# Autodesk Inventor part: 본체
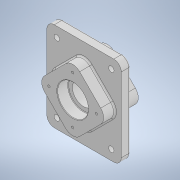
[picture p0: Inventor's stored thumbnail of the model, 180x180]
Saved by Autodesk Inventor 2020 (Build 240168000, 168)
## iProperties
Created: 2021-07
Part Number: 본체
Material: 일반
Document SubType Name: Modeling
Designer: Owner
Density: 1 g/cm^3
Appearance: 기본값
Mass: 807.977 g
Surface Area: 961.758 cm^2
Volume: 807.977 cm^3
Author: Owner
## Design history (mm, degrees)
sketch "스케치1"
  geometry: L1 (-75, -90)-(75, -90); L2 (75, -90)-(75, 90); L3 (75, 90)-(-75, 90); L4 (-75, 90)-(-75, -90); L5 (-75, -90)-(75, 90); L6 (75, -90)-(-75, 90); 1 further point
  constraints: 12 end point, 2 midpoint, 2 parallel, 1 horizontal, 1 perpendicular
  dimensions: "d0" = 150 distance of L3.end L2.end; "d1" = 180 distance of L2.end L1.end
extrude "돌출1" new body sketch "스케치1" stored distance "d2" = 18; taper "d3" = 0 deg
sketch "스케치2"
  geometry: L1 (0, 70.711)-(-70.711, 0); L2 (-70.711, 0)-(0, -70.711); L3 (0, -70.711)-(70.711, 0); L4 (70.711, 0)-(0, 70.711); L5 (0, 70.711)-(0, -70.711); L6 (-70.711, 0)-(70.711, 0); 4 further points
  constraints: 12 end point, 4 midpoint, 2 parallel, 1 coincident, 1 perpendicular, 1 vertical alignment
  dimensions: "d4" = 90 deg angle of L6 L5; "d5" = 100 distance of L1.start L1.end
extrude "돌출2" join sketch "스케치2" distance "d6" = 23; taper "d7" = 0 deg
sketch "스케치3"
  geometry: L1 (0, -70.711)-(-70.711, 0) reference; L2 (-70.711, 0)-(0, 70.711) reference; L3 (0, 70.711)-(70.711, 0) reference; L4 (70.711, 0)-(0, -70.711) reference; 1 further point
extrude "돌출3" join sketch "스케치3" distance "d8" = 29; taper "d9" = 0 deg
fillet "모깎기1" dims "d10" = 15
fillet "모깎기2" dims "d11" = 20
fillet "모깎기3" dims "d12" = 20
sketch "스케치4"
  geometry: 2 further points
  constraints: 1 coincident
hole "구멍1" sketch "스케치4" at (0, 0) diameter "d13" = 45; stored, may be unused: countersink angle "d17" = 90 deg, drill point angle "d19" = 0 deg; dims "d14" = 6, "d15" = 62, "d16" = 22, "d18" = 40
sketch "스케치5"
  geometry: 2 further points
  constraints: 1 coincident
hole "구멍2" sketch "스케치5" at (0, 0) diameter "d20" = 45; stored, may be unused: countersink angle "d24" = 90 deg, drill point angle "d26" = 0 deg; dims "d21" = 6, "d22" = 62, "d23" = 22, "d25" = 40
sketch "스케치8"
  geometry: 2 further points
  constraints: 1 vertical alignment
  dimensions: "d37" = 48 distance of point (0, 0) point (0, 48)
hole "구멍4" sketch "스케치8" at (0, 48) diameter "d38" = 4.917; stored, may be unused: countersink angle "d42" = 90 deg, drill point angle "d44" = 118 deg; dims "d39" = 10, "d40" = 62, "d41" = 22, "d43" = 13
sketch "스케치9"
  geometry: C1 r 2.458 at (0, 48) reference; 2 further points
  constraints: 1 coincident
hole "구멍5" sketch "스케치9" at (0, 48) diameter "d48" = 4.917; stored, may be unused: countersink angle "d52" = 90 deg, drill point angle "d54" = 118 deg; dims "d49" = 10, "d50" = 62, "d51" = 22, "d53" = 13
chamfer "모따기1" distance "d58" = 1; stored, may be unused: second distance "d59" = 2, angle "d60" = 45 deg
fillet "모깎기4" dims "d61" = 3
fillet "모깎기5" dims "d62" = 3
sketch "스케치10"
  geometry: C1 r 11 at (-55, 70); 1 further point
  constraints: 1 centre point
  dimensions: "d64" = 22 diameter of C1; "d65" = 70 vertical distance of point (0, 0) C1.centre; "d66" = 55 horizontal distance of point (0, 0) C1.centre
extrude "돌출5" join sketch "스케치10" distance "d67" = 5; taper "d68" = 0 deg
sketch "스케치11"
  geometry: C1 r 11 at (0, 0) reference; C2 r 11 at (0, -140) reference; C3 r 11 at (110, -140) reference; C4 r 11 at (110, 0) reference; 5 further points
  constraints: 4 coincident
hole "구멍6" sketch "스케치11" at (0, 0), (0, -140), (110, -140), (110, 0) diameter "d69" = 11; stored, may be unused: countersink angle "d73" = 90 deg, drill point angle "d75" = 118 deg; dims "d70" = 10, "d71" = 62, "d72" = 22, "d74" = 13
fillet "모깎기7" dims "d76" = 3
fillet "모깎기8" dims "d77" = 3
fillet "모깎기9" dims "d78" = 1
sketch "스케치12"
  geometry: L1 (60, 90)-(-60, 90) reference; 2 further points
  constraints: 1 vertical alignment, 1 other
  dimensions: "d79" = 15 distance from line of L1 point (0, 75)
feature "엠보싱1" sketch "스케치12" dims "d0" = 150, "d1" = 180, "d80" = 0.5, "d81" = 0
node "솔리드1"
pattern_circular "원형 패턴1" dims angle "d46" = 360 deg
pattern_circular "원형 패턴2" dims angle "d56" = 360 deg
mirror "미러5"
mirror "미러6"
node "투영된 루프1"
feature "A9D066F2-1C7D-4E18-AEED-F7BC21143FA4" dims "d13" = 45, "d14" = 6, "d15" = 62, "d16" = 22, "d17" = 90 deg, "d18" = 40, "d19" = 0
